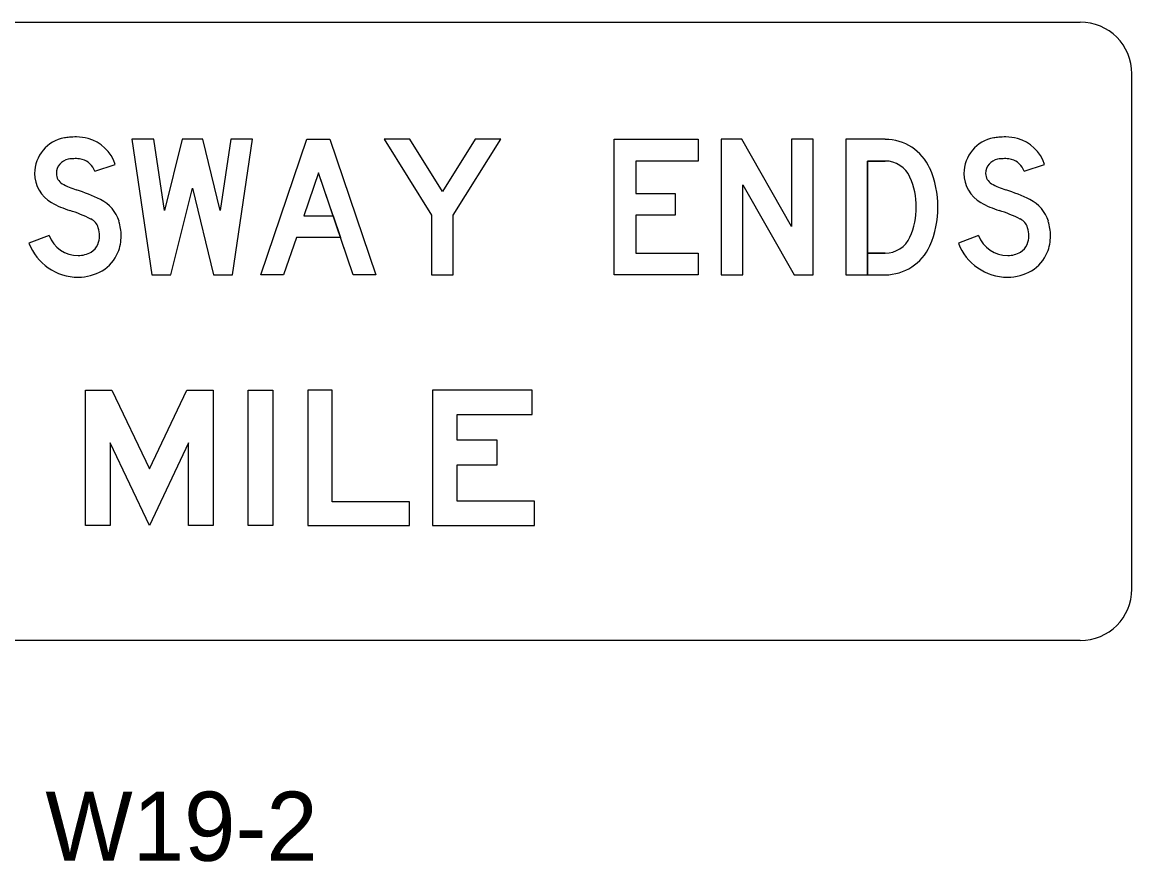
# Model space of a CAD drawing. Extents: x 42133 to 45533, y 41351 to 47951.
# Drawn here: x 44757.2 to 44877.5, y 46081 to 46172.1 of the extents above; entities that cross this region are included whole.
import ezdxf

# ---------------------------------------------------------------- set-up
doc = ezdxf.new("R2010")
doc.units = 0
doc.layers.add('P_TRAF_SIGN_SignDetails', color=7, linetype='Continuous')

msp = doc.modelspace()

# ---------------------------------------------------------------- linework, layer by layer
at = {"layer": 'P_TRAF_SIGN_SignDetails'}
for p, q in [((44683.06, 46172.1), (44871.92, 46172.1)), ((44877.49, 46166.51), (44877.49, 46110.62)), ((44850.76, 46159.4), (44846.49, 46159.4)), ((44850.76, 46157.04), (44848.85, 46157.04)), ((44850.76, 46147.05), (44848.85, 46147.05)), ((44850.76, 46147.05), (44848.85, 46147.05)), ((44871.92, 46105.03), (44683.06, 46105.03))]:
    msp.add_line(p, q, dxfattribs=at)
for points in [[(44773.31, 46144.7), (44775.63, 46154.1), (44777.94, 46144.7), (44780, 46144.7), (44782.17, 46159.4), (44779.79, 46159.4), (44778.65, 46151.66), (44776.75, 46159.4), (44774.51, 46159.4), (44772.6, 46151.66), (44771.46, 46159.4), (44769.08, 46159.4), (44771.25, 46144.7)], [(44773.31, 46144.7), (44775.63, 46154.1), (44777.94, 46144.7), (44780, 46144.7), (44782.17, 46159.4), (44779.79, 46159.4), (44778.65, 46151.66), (44776.75, 46159.4), (44774.51, 46159.4), (44772.6, 46151.66), (44771.46, 46159.4), (44769.08, 46159.4), (44771.25, 46144.7)], [(44773.31, 46144.7), (44775.63, 46154.1), (44777.94, 46144.7), (44780, 46144.7), (44782.17, 46159.4), (44779.79, 46159.4), (44778.65, 46151.66), (44776.75, 46159.4), (44774.51, 46159.4), (44772.6, 46151.66), (44771.46, 46159.4), (44769.08, 46159.4), (44771.25, 46144.7)], [(44786.91, 46148.74), (44785.53, 46144.7), (44783.05, 46144.7), (44788.05, 46159.4), (44790.55, 46159.4), (44795.54, 46144.7), (44793.06, 46144.7), (44791.69, 46148.74)], [(44783.05, 46144.7), (44788.05, 46159.4), (44790.55, 46159.4), (44795.54, 46144.7), (44793.06, 46144.7), (44789.3, 46155.76), (44787.71, 46151.09), (44790.89, 46151.09), (44791.69, 46148.74), (44786.91, 46148.74), (44785.53, 46144.7)], [(44783.05, 46144.7), (44788.05, 46159.4), (44790.55, 46159.4), (44795.54, 46144.7), (44793.06, 46144.7), (44789.3, 46155.76), (44787.71, 46151.09), (44790.89, 46151.09), (44791.69, 46148.74), (44786.91, 46148.74), (44785.53, 46144.7)], [(44801.57, 46144.7), (44803.92, 46144.7), (44803.92, 46151.16), (44809.07, 46159.4), (44806.29, 46159.4), (44802.75, 46153.72), (44799.2, 46159.4), (44796.43, 46159.4), (44801.57, 46151.16)], [(44801.57, 46144.7), (44803.92, 46144.7), (44803.92, 46151.16), (44809.07, 46159.4), (44806.29, 46159.4), (44802.75, 46153.72), (44799.2, 46159.4), (44796.43, 46159.4), (44801.57, 46151.16)], [(44801.57, 46144.7), (44803.92, 46144.7), (44803.92, 46151.16), (44809.07, 46159.4), (44806.29, 46159.4), (44802.75, 46153.72), (44799.2, 46159.4), (44796.43, 46159.4), (44801.57, 46151.16)], [(44830.47, 46157.04), (44823.71, 46157.04), (44823.71, 46153.52), (44827.98, 46153.52), (44827.98, 46151.16), (44823.71, 46151.16), (44823.71, 46147.05), (44830.47, 46147.05), (44830.47, 46144.7), (44821.36, 46144.7), (44821.36, 46159.4), (44830.47, 46159.4)], [(44830.47, 46157.04), (44823.71, 46157.04), (44823.71, 46153.52), (44827.98, 46153.52), (44827.98, 46151.16), (44823.71, 46151.16), (44823.71, 46147.05), (44830.47, 46147.05), (44830.47, 46144.7), (44821.36, 46144.7), (44821.36, 46159.4), (44830.47, 46159.4)], [(44830.47, 46157.04), (44823.71, 46157.04), (44823.71, 46153.52), (44827.98, 46153.52), (44827.98, 46151.16), (44823.71, 46151.16), (44823.71, 46147.05), (44830.47, 46147.05), (44830.47, 46144.7), (44821.36, 46144.7), (44821.36, 46159.4), (44830.47, 46159.4)], [(44842.97, 46144.7), (44842.97, 46159.4), (44840.61, 46159.4), (44840.61, 46149.95), (44835.22, 46159.4), (44832.97, 46159.4), (44832.97, 46144.7), (44835.32, 46144.7), (44835.32, 46154.47), (44840.91, 46144.7)], [(44842.97, 46144.7), (44842.97, 46159.4), (44840.61, 46159.4), (44840.61, 46149.95), (44835.22, 46159.4), (44832.97, 46159.4), (44832.97, 46144.7), (44835.32, 46144.7), (44835.32, 46154.47), (44840.91, 46144.7)], [(44842.97, 46144.7), (44842.97, 46159.4), (44840.61, 46159.4), (44840.61, 46149.95), (44835.22, 46159.4), (44832.97, 46159.4), (44832.97, 46144.7), (44835.32, 46144.7), (44835.32, 46154.47), (44840.91, 46144.7)], [(44787.71, 46151.09), (44790.89, 46151.09), (44789.3, 46155.76)], [(44770.97, 46123.66), (44775.03, 46132.2), (44777.88, 46132.2), (44777.88, 46117.5), (44775.23, 46117.5), (44775.23, 46126.47), (44770.97, 46117.5), (44766.7, 46126.47), (44766.7, 46117.5), (44764.06, 46117.5), (44764.06, 46132.2), (44766.91, 46132.2)], [(44770.97, 46123.66), (44775.03, 46132.2), (44777.88, 46132.2), (44777.88, 46117.5), (44775.23, 46117.5), (44775.23, 46126.47), (44770.97, 46117.5), (44766.7, 46126.47), (44766.7, 46117.5), (44764.06, 46117.5), (44764.06, 46132.2), (44766.91, 46132.2)], [(44770.97, 46123.66), (44775.03, 46132.2), (44777.88, 46132.2), (44777.88, 46117.5), (44775.23, 46117.5), (44775.23, 46126.47), (44770.97, 46117.5), (44766.7, 46126.47), (44766.7, 46117.5), (44764.06, 46117.5), (44764.06, 46132.2), (44766.91, 46132.2)], [(44781.7, 46117.5), (44781.7, 46132.2), (44784.34, 46132.2), (44784.34, 46117.5)], [(44781.7, 46117.5), (44781.7, 46132.2), (44784.34, 46132.2), (44784.34, 46117.5)], [(44781.7, 46117.5), (44781.7, 46132.2), (44784.34, 46132.2), (44784.34, 46117.5)], [(44799.19, 46117.5), (44799.19, 46120.07), (44790.81, 46120.07), (44790.81, 46132.2), (44788.17, 46132.2), (44788.17, 46117.5)], [(44799.19, 46117.5), (44799.19, 46120.07), (44790.81, 46120.07), (44790.81, 46132.2), (44788.17, 46132.2), (44788.17, 46117.5)], [(44799.19, 46117.5), (44799.19, 46120.07), (44790.81, 46120.07), (44790.81, 46132.2), (44788.17, 46132.2), (44788.17, 46117.5)], [(44812.72, 46120.15), (44804.34, 46120.15), (44804.34, 46124.1), (44808.67, 46124.1), (44808.67, 46126.75), (44804.34, 46126.75), (44804.34, 46129.55), (44812.49, 46129.55), (44812.49, 46132.2), (44801.69, 46132.2), (44801.69, 46117.5), (44812.72, 46117.5)], [(44812.72, 46120.15), (44804.34, 46120.15), (44804.34, 46124.1), (44808.67, 46124.1), (44808.67, 46126.75), (44804.34, 46126.75), (44804.34, 46129.55), (44812.49, 46129.55), (44812.49, 46132.2), (44801.69, 46132.2), (44801.69, 46117.5), (44812.72, 46117.5)], [(44812.72, 46120.15), (44804.34, 46120.15), (44804.34, 46124.1), (44808.67, 46124.1), (44808.67, 46126.75), (44804.34, 46126.75), (44804.34, 46129.55), (44812.49, 46129.55), (44812.49, 46132.2), (44801.69, 46132.2), (44801.69, 46117.5), (44812.72, 46117.5)]]:
    msp.add_lwpolyline(points, close=True, dxfattribs=at)
for points in [[(44846.49, 46159.4), (44846.49, 46144.7), (44850.76, 46144.7)], [(44850.76, 46159.4), (44846.49, 46159.4), (44846.49, 46144.7), (44848.85, 46144.7), (44848.85, 46157.04), (44850.76, 46157.04)], [(44850.76, 46159.4), (44846.49, 46159.4), (44846.49, 46144.7), (44848.85, 46144.7), (44848.85, 46157.04), (44850.76, 46157.04)], [(44765.04, 46155.93), (44767.27, 46156.68)], [(44765.04, 46155.93), (44767.27, 46156.68)], [(44765.04, 46155.93), (44767.27, 46156.68)], [(44848.85, 46157.04), (44848.85, 46147.05), (44850.76, 46147.05)], [(44865.82, 46155.93), (44868.05, 46156.68)], [(44865.82, 46155.93), (44868.05, 46156.68)], [(44865.82, 46155.93), (44868.05, 46156.68)], [(44760.11, 46148.97), (44757.91, 46148.14)], [(44760.11, 46148.97), (44757.91, 46148.14)], [(44760.11, 46148.97), (44757.91, 46148.14)], [(44860.9, 46148.97), (44858.7, 46148.14)], [(44860.9, 46148.97), (44858.7, 46148.14)], [(44860.9, 46148.97), (44858.7, 46148.14)], [(44848.85, 46147.05), (44848.85, 46144.7), (44850.76, 46144.7)], [(44848.85, 46147.05), (44848.85, 46144.7), (44850.76, 46144.7)]]:
    msp.add_lwpolyline(points, dxfattribs=at)
for centre, radius, start, end in [((44871.92, 46166.51), 5.59, 360, 90), ((44762.44, 46155.69), 3.92, 100.066, 180), ((44762.44, 46155.69), 3.92, 100.066, 180), ((44762.44, 46155.69), 3.92, 100.066, 180), ((44762.87, 46153.27), 6.38, 95.2021, 100.066), ((44762.87, 46153.27), 6.38, 95.2021, 100.066), ((44762.87, 46153.27), 6.38, 95.2021, 100.066), ((44763.07, 46151.1), 8.55, 90, 95.2021), ((44763.07, 46151.1), 8.55, 90, 95.2021), ((44763.07, 46151.1), 8.55, 90, 95.2021), ((44763.07, 46154.97), 4.68, 74.4676, 90), ((44763.07, 46154.97), 4.68, 74.4676, 90), ((44763.07, 46154.97), 4.68, 74.4676, 90), ((44763.16, 46155.31), 4.33, 18.4342, 74.4676), ((44763.16, 46155.31), 4.33, 18.4342, 74.4676), ((44763.16, 46155.31), 4.33, 18.4342, 74.4676), ((44762.44, 46155.69), 1.56, 100.066, 180), ((44762.44, 46155.69), 1.56, 100.066, 180), ((44762.44, 46155.69), 1.56, 100.066, 180), ((44762.87, 46153.27), 4.03, 95.2021, 100.066), ((44762.87, 46153.27), 4.03, 95.2021, 100.066), ((44762.87, 46153.27), 4.03, 95.2021, 100.066), ((44763.07, 46151.1), 6.2, 90, 95.2021), ((44763.07, 46151.1), 6.2, 90, 95.2021), ((44763.07, 46151.1), 6.2, 90, 95.2021), ((44763.07, 46154.97), 2.33, 74.4676, 90), ((44763.07, 46154.97), 2.33, 74.4676, 90), ((44763.07, 46154.97), 2.33, 74.4676, 90), ((44763.16, 46155.31), 1.98, 18.4342, 74.4676), ((44763.16, 46155.31), 1.98, 18.4342, 74.4676), ((44763.16, 46155.31), 1.98, 18.4342, 74.4676), ((44762.15, 46155.69), 3.62, 180, 240.5254), ((44762.15, 46155.69), 3.62, 180, 240.5254), ((44762.15, 46155.69), 3.62, 180, 240.5254), ((44762.15, 46155.69), 1.27, 180, 240.5254), ((44762.15, 46155.69), 1.27, 180, 240.5254), ((44762.15, 46155.69), 1.27, 180, 240.5254), ((44765.47, 46161.56), 8.02, 240.5254, 252.423), ((44765.47, 46161.56), 8.02, 240.5254, 252.423), ((44765.47, 46161.56), 8.02, 240.5254, 252.423), ((44757.53, 46136.52), 18.25, 63.4948, 72.423), ((44757.53, 46136.52), 18.25, 63.4948, 72.423), ((44757.53, 46136.52), 18.25, 63.4948, 72.423), ((44765.47, 46161.56), 10.37, 240.5254, 252.423), ((44765.47, 46161.56), 10.37, 240.5254, 252.423), ((44765.47, 46161.56), 10.37, 240.5254, 252.423), ((44763.93, 46149.35), 3.92, 17.0924, 63.4948), ((44763.93, 46149.35), 3.92, 17.0924, 63.4948), ((44763.93, 46149.35), 3.92, 17.0924, 63.4948), ((44757.53, 46136.52), 15.9, 63.4948, 72.423), ((44757.53, 46136.52), 15.9, 63.4948, 72.423), ((44757.53, 46136.52), 15.9, 63.4948, 72.423), ((44763.93, 46149.35), 1.57, 17.0924, 63.4948), ((44763.93, 46149.35), 1.57, 17.0924, 63.4948), ((44763.93, 46149.35), 1.57, 17.0924, 63.4948), ((44762.59, 46148.93), 2.97, 360, 17.0924), ((44762.59, 46148.93), 2.97, 360, 17.0924), ((44762.59, 46148.93), 2.97, 360, 17.0924), ((44762.59, 46148.93), 5.32, 0, 17.0924), ((44762.59, 46148.93), 5.32, 360, 17.0924), ((44762.59, 46148.93), 5.32, 0, 17.0924), ((44763.26, 46150.16), 3.37, 200.654, 270), ((44763.26, 46150.16), 3.37, 200.654, 270), ((44763.26, 46150.16), 3.37, 200.654, 270), ((44763.05, 46148.93), 2.51, 338.164, 0), ((44763.05, 46148.93), 2.51, 338.164, 0), ((44763.05, 46148.93), 2.51, 338.164, 0), ((44763.05, 46148.93), 4.86, 338.164, 360), ((44763.05, 46148.93), 4.86, 338.164, 0), ((44763.05, 46148.93), 4.86, 338.164, 0), ((44763.26, 46150.16), 5.72, 200.654, 270), ((44763.26, 46150.16), 5.72, 200.654, 270), ((44763.26, 46150.16), 5.72, 200.654, 270), ((44763.26, 46149.55), 2.76, 270, 300.4201), ((44763.26, 46149.55), 2.76, 270, 300.4201), ((44763.26, 46149.55), 2.76, 270, 300.4201), ((44763.8, 46148.63), 1.7, 300.4201, 338.164), ((44763.8, 46148.63), 1.7, 300.4201, 338.164), ((44763.8, 46148.63), 1.7, 300.4201, 338.164), ((44763.8, 46148.63), 4.05, 300.4201, 338.164), ((44763.8, 46148.63), 4.05, 300.4201, 338.164), ((44763.8, 46148.63), 4.05, 300.4201, 338.164), ((44763.26, 46149.55), 5.11, 270, 300.4201), ((44763.26, 46149.55), 5.11, 270, 300.4201), ((44763.26, 46149.55), 5.11, 270, 300.4201), ((44871.92, 46110.62), 5.59, 270, 360)]:
    msp.add_arc(centre, radius, start, end, dxfattribs=at)
for centre, major_axis, ratio, start_param, end_param in [((44850.76, 46154.1), (0, 5.29), 0.999993, 5.13024, 6.283185), ((44850.76, 46154.1), (0, 5.29), 0.999993, 5.13024, 6.283185), ((44850.76, 46154.1), (0, 5.29), 0.999993, 5.13024, 6.283185), ((44863.22, 46155.69), (0, 3.92), 0.999994, 0.175685, 1.570796), ((44863.22, 46155.69), (0, 3.92), 0.999994, 0.175685, 1.570796), ((44863.22, 46155.69), (0, 3.92), 0.999994, 0.175685, 1.570796), ((44863.65, 46153.27), (0, 6.38), 0.999994, 0.090794, 0.175685), ((44863.65, 46153.27), (0, 6.38), 0.999994, 0.090794, 0.175685), ((44863.65, 46153.27), (0, 6.38), 0.999994, 0.090794, 0.175685), ((44863.85, 46151.1), (0, 8.55), 0.999994, 6.283185, 6.373979), ((44863.85, 46151.1), (0, 8.55), 0.999994, 6.283185, 6.373979), ((44863.85, 46151.1), (0, 8.55), 0.999994, 6.283185, 6.373979), ((44863.85, 46154.97), (0, 4.68), 0.999994, 6.012094, 6.283185), ((44863.85, 46154.97), (0, 4.68), 0.999994, 6.012094, 6.283185), ((44863.85, 46154.97), (0, 4.68), 0.999994, 6.012094, 6.283185), ((44863.94, 46155.31), (0, 4.33), 0.999994, 5.034126, 6.012094), ((44863.94, 46155.31), (0, 4.33), 0.999994, 5.034126, 6.012094), ((44863.94, 46155.31), (0, 4.33), 0.999994, 5.034126, 6.012094), ((44850.76, 46154.1), (0, 2.94), 0.999993, 5.13024, 6.283185), ((44850.76, 46154.1), (0, 2.94), 0.999993, 5.13024, 6.283185), ((44850.76, 46154.1), (0, 2.94), 0.999993, 5.13024, 6.283185), ((44863.22, 46155.69), (0, 1.56), 0.999994, 0.175685, 1.570796), ((44863.22, 46155.69), (0, 1.56), 0.999994, 0.175685, 1.570796), ((44863.22, 46155.69), (0, 1.56), 0.999994, 0.175685, 1.570796), ((44863.65, 46153.27), (0, 4.03), 0.999994, 0.090794, 0.175685), ((44863.65, 46153.27), (0, 4.03), 0.999994, 0.090794, 0.175685), ((44863.65, 46153.27), (0, 4.03), 0.999994, 0.090794, 0.175685), ((44863.85, 46151.1), (0, 6.2), 0.999994, 0, 0.090794), ((44863.85, 46151.1), (0, 6.2), 0.999994, 0, 0.090794), ((44863.85, 46151.1), (0, 6.2), 0.999994, 0, 0.090794), ((44863.85, 46154.97), (0, 2.33), 0.999994, 6.012094, 6.283185), ((44863.85, 46154.97), (0, 2.33), 0.999994, 6.012094, 6.283185), ((44863.85, 46154.97), (0, 2.33), 0.999994, 6.012094, 6.283185), ((44863.94, 46155.31), (0, 1.98), 0.999994, 5.034126, 6.012094), ((44863.94, 46155.31), (0, 1.98), 0.999994, 5.034126, 6.012094), ((44863.94, 46155.31), (0, 1.98), 0.999994, 5.034126, 6.012094), ((44846.13, 46152.05), (0, 10.36), 0.999993, 4.294538, 5.13024), ((44846.13, 46152.05), (0, 10.36), 0.999993, 4.294538, 5.13024), ((44846.13, 46152.05), (0, 10.36), 0.999993, 4.294538, 5.13024), ((44862.93, 46155.69), (0, 3.62), 0.999994, 1.570796, 2.627164), ((44862.93, 46155.69), (0, 3.62), 0.999994, 1.570796, 2.627164), ((44862.93, 46155.69), (0, 3.62), 0.999994, 1.570796, 2.627164), ((44862.93, 46155.69), (0, 1.27), 0.999994, 1.570796, 2.627164), ((44862.93, 46155.69), (0, 1.27), 0.999994, 1.570796, 2.627164), ((44862.93, 46155.69), (0, 1.27), 0.999994, 1.570796, 2.627164), ((44846.13, 46152.05), (0, 8.01), 0.999993, 4.294538, 5.13024), ((44846.13, 46152.05), (0, 8.01), 0.999993, 4.294538, 5.13024), ((44846.13, 46152.05), (0, 8.01), 0.999993, 4.294538, 5.13024), ((44866.25, 46161.56), (0, 8.02), 0.999994, 2.627164, 2.834816), ((44866.25, 46161.56), (0, 8.02), 0.999994, 2.627164, 2.834816), ((44866.25, 46161.56), (0, 8.02), 0.999994, 2.627164, 2.834816), ((44858.32, 46136.52), (0, 18.25), 0.999994, 5.820582, 5.976409), ((44858.32, 46136.52), (0, 18.25), 0.999994, 5.820582, 5.976409), ((44858.32, 46136.52), (0, 18.25), 0.999994, 5.820582, 5.976409), ((44866.25, 46161.56), (0, 10.37), 0.999994, 2.627164, 2.834816), ((44866.25, 46161.56), (0, 10.37), 0.999994, 2.627164, 2.834816), ((44866.25, 46161.56), (0, 10.37), 0.999994, 2.627164, 2.834816), ((44864.71, 46149.35), (0, 3.92), 0.999994, 5.010707, 5.820582), ((44864.71, 46149.35), (0, 3.92), 0.999994, 5.010707, 5.820582), ((44864.71, 46149.35), (0, 3.92), 0.999994, 5.010707, 5.820582), ((44858.32, 46136.52), (0, 15.9), 0.999994, 5.820582, 5.976409), ((44858.32, 46136.52), (0, 15.9), 0.999994, 5.820582, 5.976409), ((44858.32, 46136.52), (0, 15.9), 0.999994, 5.820582, 5.976409), ((44864.71, 46149.35), (0, 1.57), 0.999994, 5.010707, 5.820582), ((44864.71, 46149.35), (0, 1.57), 0.999994, 5.010707, 5.820582), ((44864.71, 46149.35), (0, 1.57), 0.999994, 5.010707, 5.820582), ((44863.37, 46148.93), (0, 2.97), 0.999994, 4.712389, 5.010707), ((44863.37, 46148.93), (0, 2.97), 0.999994, 4.712389, 5.010707), ((44863.37, 46148.93), (0, 2.97), 0.999994, 4.712389, 5.010707), ((44863.37, 46148.93), (0, 5.32), 0.999994, 4.712389, 5.010707), ((44863.37, 46148.93), (0, 5.32), 0.999994, 4.712389, 5.010707), ((44863.37, 46148.93), (0, 5.32), 0.999994, 4.712389, 5.010707), ((44850.76, 46149.99), (0, 2.94), 0.999993, 3.141593, 4.294538), ((44850.76, 46149.99), (0, 2.94), 0.999993, 3.141593, 4.294538), ((44850.76, 46149.99), (0, 2.94), 0.999993, 3.141593, 4.294538), ((44864.05, 46150.16), (0, 3.37), 0.999994, 1.931277, 3.141593), ((44864.05, 46150.16), (0, 3.37), 0.999994, 1.931277, 3.141593), ((44864.05, 46150.16), (0, 3.37), 0.999994, 1.931277, 3.141593), ((44863.83, 46148.93), (0, 2.51), 0.999994, 4.331279, 4.712389), ((44863.83, 46148.93), (0, 2.51), 0.999994, 4.331279, 4.712389), ((44863.83, 46148.93), (0, 2.51), 0.999994, 4.331279, 4.712389), ((44863.83, 46148.93), (0, 4.86), 0.999994, 4.331279, 4.712389), ((44863.83, 46148.93), (0, 4.86), 0.999994, 4.331279, 4.712389), ((44863.83, 46148.93), (0, 4.86), 0.999994, 4.331279, 4.712389), ((44850.76, 46149.99), (0, 5.29), 0.999993, 3.141593, 4.294538), ((44850.76, 46149.99), (0, 5.29), 0.999993, 3.141593, 4.294538), ((44850.76, 46149.99), (0, 5.29), 0.999993, 3.141593, 4.294538), ((44864.05, 46150.16), (0, 5.72), 0.999994, 1.931277, 3.141593), ((44864.05, 46150.16), (0, 5.72), 0.999994, 1.931277, 3.141593), ((44864.05, 46150.16), (0, 5.72), 0.999994, 1.931277, 3.141593), ((44864.05, 46149.55), (0, 2.76), 0.999994, 3.141593, 3.672524), ((44864.05, 46149.55), (0, 2.76), 0.999994, 3.141593, 3.672524), ((44864.05, 46149.55), (0, 2.76), 0.999994, 3.141593, 3.672524), ((44864.58, 46148.63), (0, 1.7), 0.999994, 3.672524, 4.331279), ((44864.58, 46148.63), (0, 1.7), 0.999994, 3.672524, 4.331279), ((44864.58, 46148.63), (0, 1.7), 0.999994, 3.672524, 4.331279), ((44864.58, 46148.63), (0, 4.05), 0.999994, 3.672524, 4.331279), ((44864.58, 46148.63), (0, 4.05), 0.999994, 3.672524, 4.331279), ((44864.58, 46148.63), (0, 4.05), 0.999994, 3.672524, 4.331279), ((44864.05, 46149.55), (0, 5.11), 0.999994, 3.141593, 3.672524), ((44864.05, 46149.55), (0, 5.11), 0.999994, 3.141593, 3.672524), ((44864.05, 46149.55), (0, 5.11), 0.999994, 3.141593, 3.672524)]:
    msp.add_ellipse(centre, major_axis=major_axis, ratio=ratio, start_param=start_param, end_param=end_param, dxfattribs=at)

# ---------------------------------------------------------------- texts
msp.add_text('W19-2', height=7.5, dxfattribs=at).set_placement((44759.69, 46081.14))

doc.saveas('drawing.dxf')
